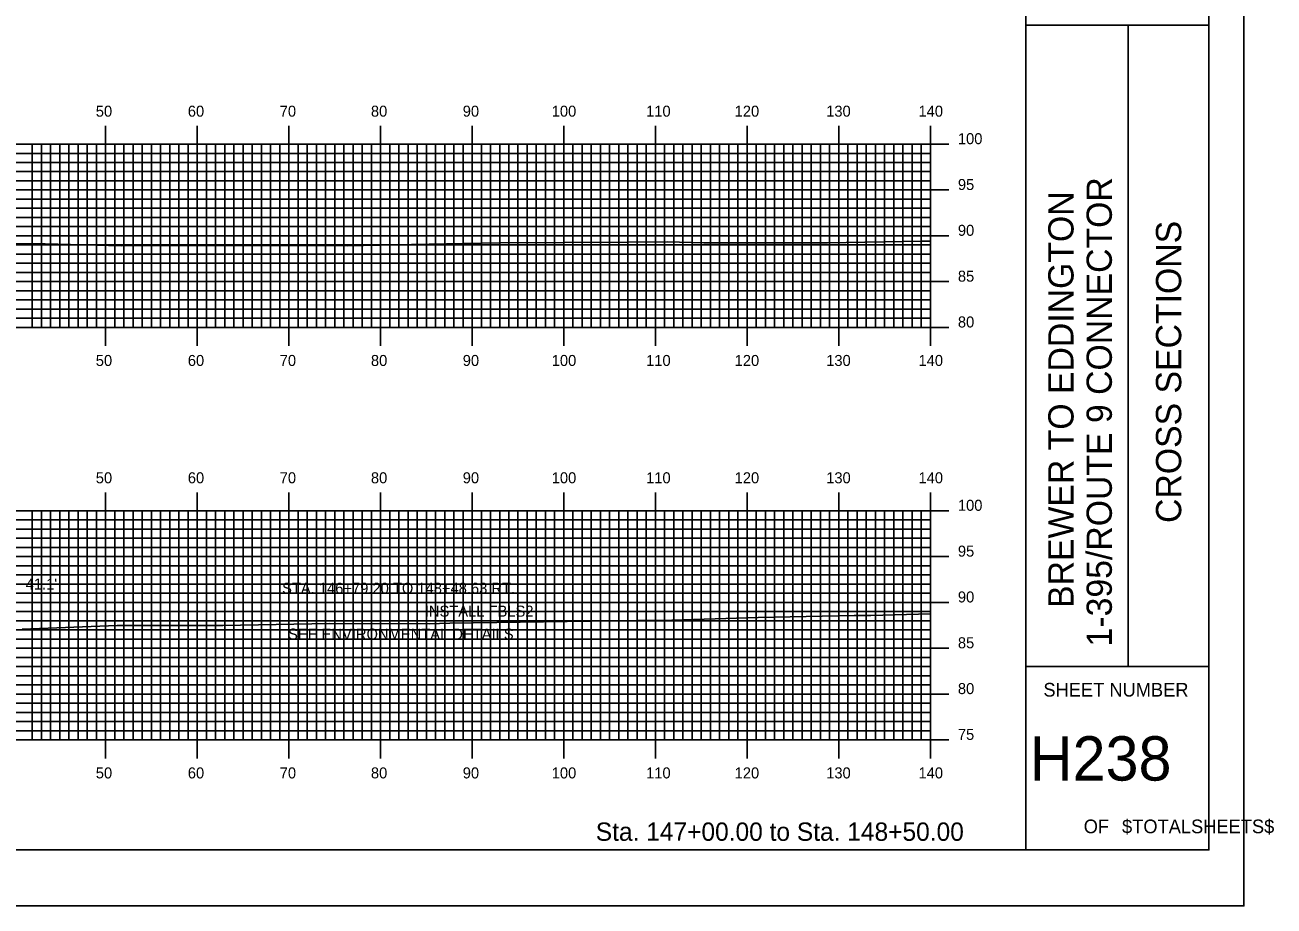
# Model space of a CAD drawing. Extents: x 1777925 to 1778268, y 442591 to 442811.
# Drawn here: x 1778132 to 1778268.3, y 442590.5 to 442686.7 of the extents above; entities that cross this region are included whole.
import ezdxf

# ---------------------------------------------------------------- set-up
doc = ezdxf.new("R2010")
doc.units = 0
for name, color, linetype in [('BORDER', 7, 'Continuous'), ('D_Text_Standard', 7, 'Continuous'), ('H_V ANNOTATION', 7, 'Continuous'), ('MAJOR', 7, 'Continuous'), ('MINOR', 7, 'Continuous'), ('PLOT BOUNDARY', 7, 'Continuous'), ('S_Roadway_Centerline', 7, 'Continuous')]:
    doc.layers.add(name, color=color, linetype=linetype)

msp = doc.modelspace()

# ---------------------------------------------------------------- linework, layer by layer
at = {"layer": 'BORDER'}
for p, q in [((1778241.19, 442596.67), (1778241.19, 442806.67)), ((1778241.19, 442686.67), (1778261.19, 442686.67)), ((1778252.37, 442616.67), (1778252.37, 442686.67)), ((1778241.19, 442616.67), (1778261.19, 442616.67))]:
    msp.add_line(p, q, dxfattribs=at)
msp.add_lwpolyline([(1777941.19, 442596.67), (1778261.19, 442596.67), (1778261.19, 442806.67), (1777941.19, 442806.67)], close=True, dxfattribs=at)
at = {"layer": 'MAJOR'}
for p, q in [((1778140.79, 442675.67), (1778140.79, 442673.67)), ((1778150.79, 442675.67), (1778150.79, 442673.67)), ((1778160.79, 442675.67), (1778160.79, 442673.67)), ((1778170.79, 442675.67), (1778170.79, 442673.67)), ((1778180.79, 442675.67), (1778180.79, 442673.67)), ((1778190.79, 442675.67), (1778190.79, 442673.67)), ((1778200.79, 442675.67), (1778200.79, 442673.67)), ((1778210.79, 442675.67), (1778210.79, 442673.67)), ((1778220.79, 442675.67), (1778220.79, 442673.67)), ((1778230.79, 442675.67), (1778230.79, 442673.67)), ((1777950.79, 442673.67), (1778230.79, 442673.67)), ((1777950.79, 442673.67), (1778230.79, 442673.67)), ((1778140.79, 442653.67), (1778140.79, 442673.67)), ((1778150.79, 442653.67), (1778150.79, 442673.67)), ((1778160.79, 442653.67), (1778160.79, 442673.67)), ((1778170.79, 442653.67), (1778170.79, 442673.67)), ((1778180.79, 442653.67), (1778180.79, 442673.67)), ((1778190.79, 442653.67), (1778190.79, 442673.67)), ((1778200.79, 442653.67), (1778200.79, 442673.67)), ((1778210.79, 442653.67), (1778210.79, 442673.67)), ((1778220.79, 442653.67), (1778220.79, 442673.67)), ((1778232.79, 442673.67), (1778228.79, 442673.67)), ((1778230.79, 442653.67), (1778230.79, 442673.67)), ((1778230.79, 442653.67), (1778230.79, 442673.67)), ((1777950.79, 442668.67), (1778230.79, 442668.67)), ((1778232.79, 442668.67), (1778228.79, 442668.67)), ((1777950.79, 442663.67), (1778230.79, 442663.67)), ((1778232.79, 442663.67), (1778228.79, 442663.67)), ((1777950.79, 442658.67), (1778230.79, 442658.67)), ((1778232.79, 442658.67), (1778228.79, 442658.67)), ((1777950.79, 442653.67), (1778230.79, 442653.67)), ((1777950.79, 442653.67), (1778230.79, 442653.67)), ((1778140.79, 442651.66), (1778140.79, 442653.67)), ((1778150.79, 442651.66), (1778150.79, 442653.67)), ((1778160.79, 442651.66), (1778160.79, 442653.67)), ((1778170.79, 442651.66), (1778170.79, 442653.67)), ((1778180.79, 442651.66), (1778180.79, 442653.67)), ((1778190.79, 442651.66), (1778190.79, 442653.67)), ((1778200.79, 442651.66), (1778200.79, 442653.67)), ((1778210.79, 442651.66), (1778210.79, 442653.67)), ((1778220.79, 442651.66), (1778220.79, 442653.67)), ((1778232.79, 442653.67), (1778228.79, 442653.67)), ((1778230.79, 442651.66), (1778230.79, 442653.67)), ((1778140.79, 442635.67), (1778140.79, 442633.67)), ((1778150.79, 442635.67), (1778150.79, 442633.67)), ((1778160.79, 442635.67), (1778160.79, 442633.67)), ((1778170.79, 442635.67), (1778170.79, 442633.67)), ((1778180.79, 442635.67), (1778180.79, 442633.67)), ((1778190.79, 442635.67), (1778190.79, 442633.67)), ((1778200.79, 442635.67), (1778200.79, 442633.67)), ((1778210.79, 442635.67), (1778210.79, 442633.67)), ((1778220.79, 442635.67), (1778220.79, 442633.67)), ((1778230.79, 442635.67), (1778230.79, 442633.67)), ((1777950.79, 442633.67), (1778230.79, 442633.67)), ((1777950.79, 442633.67), (1778230.79, 442633.67)), ((1778140.79, 442608.67), (1778140.79, 442633.67)), ((1778150.79, 442608.67), (1778150.79, 442633.67)), ((1778160.79, 442608.67), (1778160.79, 442633.67)), ((1778170.79, 442608.67), (1778170.79, 442633.67)), ((1778180.79, 442608.67), (1778180.79, 442633.67)), ((1778190.79, 442608.67), (1778190.79, 442633.67)), ((1778200.79, 442608.67), (1778200.79, 442633.67)), ((1778210.79, 442608.67), (1778210.79, 442633.67)), ((1778220.79, 442608.67), (1778220.79, 442633.67)), ((1778232.79, 442633.67), (1778228.79, 442633.67)), ((1778230.79, 442608.67), (1778230.79, 442633.67)), ((1778230.79, 442608.67), (1778230.79, 442633.67)), ((1777950.79, 442628.67), (1778230.79, 442628.67)), ((1778232.79, 442628.67), (1778228.79, 442628.67)), ((1777950.79, 442623.67), (1778230.79, 442623.67)), ((1778232.79, 442623.67), (1778228.79, 442623.67)), ((1777950.79, 442618.67), (1778230.79, 442618.67)), ((1778232.79, 442618.67), (1778228.79, 442618.67)), ((1777950.79, 442613.67), (1778230.79, 442613.67)), ((1778232.79, 442613.67), (1778228.79, 442613.67)), ((1777950.79, 442608.67), (1778230.79, 442608.67)), ((1777950.79, 442608.67), (1778230.79, 442608.67)), ((1778140.79, 442606.66), (1778140.79, 442608.67)), ((1778150.79, 442606.66), (1778150.79, 442608.67)), ((1778160.79, 442606.66), (1778160.79, 442608.67)), ((1778170.79, 442606.66), (1778170.79, 442608.67)), ((1778180.79, 442606.66), (1778180.79, 442608.67)), ((1778190.79, 442606.66), (1778190.79, 442608.67)), ((1778200.79, 442606.66), (1778200.79, 442608.67)), ((1778210.79, 442606.66), (1778210.79, 442608.67)), ((1778220.79, 442606.66), (1778220.79, 442608.67)), ((1778232.79, 442608.67), (1778228.79, 442608.67)), ((1778230.79, 442606.66), (1778230.79, 442608.67))]:
    msp.add_line(p, q, dxfattribs=at)
at = {"layer": 'MINOR'}
for p, q in [((1777950.79, 442672.67), (1778230.79, 442672.67)), ((1778132.79, 442653.67), (1778132.79, 442673.67)), ((1778133.79, 442653.67), (1778133.79, 442673.67)), ((1778134.79, 442653.67), (1778134.79, 442673.67)), ((1778135.79, 442653.67), (1778135.79, 442673.67)), ((1778136.79, 442653.67), (1778136.79, 442673.67)), ((1778137.79, 442653.67), (1778137.79, 442673.67)), ((1778138.79, 442653.67), (1778138.79, 442673.67)), ((1778139.79, 442653.67), (1778139.79, 442673.67)), ((1778141.79, 442653.67), (1778141.79, 442673.67)), ((1778142.79, 442653.67), (1778142.79, 442673.67)), ((1778143.79, 442653.67), (1778143.79, 442673.67)), ((1778144.79, 442653.67), (1778144.79, 442673.67)), ((1778145.79, 442653.67), (1778145.79, 442673.67)), ((1778146.79, 442653.67), (1778146.79, 442673.67)), ((1778147.79, 442653.67), (1778147.79, 442673.67)), ((1778148.79, 442653.67), (1778148.79, 442673.67)), ((1778149.79, 442653.67), (1778149.79, 442673.67)), ((1778151.79, 442653.67), (1778151.79, 442673.67)), ((1778152.79, 442653.67), (1778152.79, 442673.67)), ((1778153.79, 442653.67), (1778153.79, 442673.67)), ((1778154.79, 442653.67), (1778154.79, 442673.67)), ((1778155.79, 442653.67), (1778155.79, 442673.67)), ((1778156.79, 442653.67), (1778156.79, 442673.67)), ((1778157.79, 442653.67), (1778157.79, 442673.67)), ((1778158.79, 442653.67), (1778158.79, 442673.67)), ((1778159.79, 442653.67), (1778159.79, 442673.67)), ((1778161.79, 442653.67), (1778161.79, 442673.67)), ((1778162.79, 442653.67), (1778162.79, 442673.67)), ((1778163.79, 442653.67), (1778163.79, 442673.67)), ((1778164.79, 442653.67), (1778164.79, 442673.67)), ((1778165.79, 442653.67), (1778165.79, 442673.67)), ((1778166.79, 442653.67), (1778166.79, 442673.67)), ((1778167.79, 442653.67), (1778167.79, 442673.67)), ((1778168.79, 442653.67), (1778168.79, 442673.67)), ((1778169.79, 442653.67), (1778169.79, 442673.67)), ((1778171.79, 442653.67), (1778171.79, 442673.67)), ((1778172.79, 442653.67), (1778172.79, 442673.67)), ((1778173.79, 442653.67), (1778173.79, 442673.67)), ((1778174.79, 442653.67), (1778174.79, 442673.67)), ((1778175.79, 442653.67), (1778175.79, 442673.67)), ((1778176.79, 442653.67), (1778176.79, 442673.67)), ((1778177.79, 442653.67), (1778177.79, 442673.67)), ((1778178.79, 442653.67), (1778178.79, 442673.67)), ((1778179.79, 442653.67), (1778179.79, 442673.67)), ((1778181.79, 442653.67), (1778181.79, 442673.67)), ((1778182.79, 442653.67), (1778182.79, 442673.67)), ((1778183.79, 442653.67), (1778183.79, 442673.67)), ((1778184.79, 442653.67), (1778184.79, 442673.67)), ((1778185.79, 442653.67), (1778185.79, 442673.67)), ((1778186.79, 442653.67), (1778186.79, 442673.67)), ((1778187.79, 442653.67), (1778187.79, 442673.67)), ((1778188.79, 442653.67), (1778188.79, 442673.67)), ((1778189.79, 442653.67), (1778189.79, 442673.67)), ((1778191.79, 442653.67), (1778191.79, 442673.67)), ((1778192.79, 442653.67), (1778192.79, 442673.67)), ((1778193.79, 442653.67), (1778193.79, 442673.67)), ((1778194.79, 442653.67), (1778194.79, 442673.67)), ((1778195.79, 442653.67), (1778195.79, 442673.67)), ((1778196.79, 442653.67), (1778196.79, 442673.67)), ((1778197.79, 442653.67), (1778197.79, 442673.67)), ((1778198.79, 442653.67), (1778198.79, 442673.67)), ((1778199.79, 442653.67), (1778199.79, 442673.67)), ((1778201.79, 442653.67), (1778201.79, 442673.67)), ((1778202.79, 442653.67), (1778202.79, 442673.67)), ((1778203.79, 442653.67), (1778203.79, 442673.67)), ((1778204.79, 442653.67), (1778204.79, 442673.67)), ((1778205.79, 442653.67), (1778205.79, 442673.67)), ((1778206.79, 442653.67), (1778206.79, 442673.67)), ((1778207.79, 442653.67), (1778207.79, 442673.67)), ((1778208.79, 442653.67), (1778208.79, 442673.67)), ((1778209.79, 442653.67), (1778209.79, 442673.67)), ((1778211.79, 442653.67), (1778211.79, 442673.67)), ((1778212.79, 442653.67), (1778212.79, 442673.67)), ((1778213.79, 442653.67), (1778213.79, 442673.67)), ((1778214.79, 442653.67), (1778214.79, 442673.67)), ((1778215.79, 442653.67), (1778215.79, 442673.67)), ((1778216.79, 442653.67), (1778216.79, 442673.67)), ((1778217.79, 442653.67), (1778217.79, 442673.67)), ((1778218.79, 442653.67), (1778218.79, 442673.67)), ((1778219.79, 442653.67), (1778219.79, 442673.67)), ((1778221.79, 442653.67), (1778221.79, 442673.67)), ((1778222.79, 442653.67), (1778222.79, 442673.67)), ((1778223.79, 442653.67), (1778223.79, 442673.67)), ((1778224.79, 442653.67), (1778224.79, 442673.67)), ((1778225.79, 442653.67), (1778225.79, 442673.67)), ((1778226.79, 442653.67), (1778226.79, 442673.67)), ((1778227.79, 442653.67), (1778227.79, 442673.67)), ((1778228.79, 442653.67), (1778228.79, 442673.67)), ((1778230.79, 442672.67), (1778228.79, 442672.67)), ((1778229.79, 442653.67), (1778229.79, 442673.67)), ((1777950.79, 442671.67), (1778230.79, 442671.67)), ((1778230.79, 442671.67), (1778228.79, 442671.67)), ((1777950.79, 442670.67), (1778230.79, 442670.67)), ((1778230.79, 442670.67), (1778228.79, 442670.67)), ((1777950.79, 442669.67), (1778230.79, 442669.67)), ((1778230.79, 442669.67), (1778228.79, 442669.67)), ((1777950.79, 442667.67), (1778230.79, 442667.67)), ((1778230.79, 442667.67), (1778228.79, 442667.67)), ((1777950.79, 442666.67), (1778230.79, 442666.67)), ((1778230.79, 442666.67), (1778228.79, 442666.67)), ((1777950.79, 442665.67), (1778230.79, 442665.67)), ((1777950.79, 442664.67), (1778230.79, 442664.67)), ((1778230.79, 442665.67), (1778228.79, 442665.67)), ((1778230.79, 442664.67), (1778228.79, 442664.67)), ((1777950.79, 442662.67), (1778230.79, 442662.67)), ((1777950.79, 442661.67), (1778230.79, 442661.67)), ((1778230.79, 442662.67), (1778228.79, 442662.67)), ((1778230.79, 442661.67), (1778228.79, 442661.67)), ((1777950.79, 442660.67), (1778230.79, 442660.67)), ((1778230.79, 442660.67), (1778228.79, 442660.67)), ((1777950.79, 442659.67), (1778230.79, 442659.67)), ((1778230.79, 442659.67), (1778228.79, 442659.67)), ((1777950.79, 442657.67), (1778230.79, 442657.67)), ((1778230.79, 442657.67), (1778228.79, 442657.67)), ((1777950.79, 442656.67), (1778230.79, 442656.67)), ((1778230.79, 442656.67), (1778228.79, 442656.67)), ((1777950.79, 442655.67), (1778230.79, 442655.67)), ((1778230.79, 442655.67), (1778228.79, 442655.67)), ((1777950.79, 442654.67), (1778230.79, 442654.67)), ((1778230.79, 442654.67), (1778228.79, 442654.67)), ((1778132.79, 442608.67), (1778132.79, 442633.67)), ((1778133.79, 442608.67), (1778133.79, 442633.67)), ((1778134.79, 442608.67), (1778134.79, 442633.67)), ((1778135.79, 442608.67), (1778135.79, 442633.67)), ((1778136.79, 442608.67), (1778136.79, 442633.67)), ((1778137.79, 442608.67), (1778137.79, 442633.67)), ((1778138.79, 442608.67), (1778138.79, 442633.67)), ((1778139.79, 442608.67), (1778139.79, 442633.67)), ((1778141.79, 442608.67), (1778141.79, 442633.67)), ((1778142.79, 442608.67), (1778142.79, 442633.67)), ((1778143.79, 442608.67), (1778143.79, 442633.67)), ((1778144.79, 442608.67), (1778144.79, 442633.67)), ((1778145.79, 442608.67), (1778145.79, 442633.67)), ((1778146.79, 442608.67), (1778146.79, 442633.67)), ((1778147.79, 442608.67), (1778147.79, 442633.67)), ((1778148.79, 442608.67), (1778148.79, 442633.67)), ((1778149.79, 442608.67), (1778149.79, 442633.67)), ((1778151.79, 442608.67), (1778151.79, 442633.67)), ((1778152.79, 442608.67), (1778152.79, 442633.67)), ((1778153.79, 442608.67), (1778153.79, 442633.67)), ((1778154.79, 442608.67), (1778154.79, 442633.67)), ((1778155.79, 442608.67), (1778155.79, 442633.67)), ((1778156.79, 442608.67), (1778156.79, 442633.67)), ((1778157.79, 442608.67), (1778157.79, 442633.67)), ((1778158.79, 442608.67), (1778158.79, 442633.67)), ((1778159.79, 442608.67), (1778159.79, 442633.67)), ((1778161.79, 442608.67), (1778161.79, 442633.67)), ((1778162.79, 442608.67), (1778162.79, 442633.67)), ((1778163.79, 442608.67), (1778163.79, 442633.67)), ((1778164.79, 442608.67), (1778164.79, 442633.67)), ((1778165.79, 442608.67), (1778165.79, 442633.67)), ((1778166.79, 442608.67), (1778166.79, 442633.67)), ((1778167.79, 442608.67), (1778167.79, 442633.67)), ((1778168.79, 442608.67), (1778168.79, 442633.67)), ((1778169.79, 442608.67), (1778169.79, 442633.67)), ((1778171.79, 442608.67), (1778171.79, 442633.67)), ((1778172.79, 442608.67), (1778172.79, 442633.67)), ((1778173.79, 442608.67), (1778173.79, 442633.67)), ((1778174.79, 442608.67), (1778174.79, 442633.67)), ((1778175.79, 442608.67), (1778175.79, 442633.67)), ((1778176.79, 442608.67), (1778176.79, 442633.67)), ((1778177.79, 442608.67), (1778177.79, 442633.67)), ((1778178.79, 442608.67), (1778178.79, 442633.67)), ((1778179.79, 442608.67), (1778179.79, 442633.67)), ((1778181.79, 442608.67), (1778181.79, 442633.67)), ((1778182.79, 442608.67), (1778182.79, 442633.67)), ((1778183.79, 442608.67), (1778183.79, 442633.67)), ((1778184.79, 442608.67), (1778184.79, 442633.67)), ((1778185.79, 442608.67), (1778185.79, 442633.67)), ((1778186.79, 442608.67), (1778186.79, 442633.67)), ((1778187.79, 442608.67), (1778187.79, 442633.67)), ((1778188.79, 442608.67), (1778188.79, 442633.67)), ((1778189.79, 442608.67), (1778189.79, 442633.67)), ((1778191.79, 442608.67), (1778191.79, 442633.67)), ((1778192.79, 442608.67), (1778192.79, 442633.67)), ((1778193.79, 442608.67), (1778193.79, 442633.67)), ((1778194.79, 442608.67), (1778194.79, 442633.67)), ((1778195.79, 442608.67), (1778195.79, 442633.67)), ((1778196.79, 442608.67), (1778196.79, 442633.67)), ((1778197.79, 442608.67), (1778197.79, 442633.67)), ((1778198.79, 442608.67), (1778198.79, 442633.67)), ((1778199.79, 442608.67), (1778199.79, 442633.67)), ((1778201.79, 442608.67), (1778201.79, 442633.67)), ((1778202.79, 442608.67), (1778202.79, 442633.67)), ((1778203.79, 442608.67), (1778203.79, 442633.67)), ((1778204.79, 442608.67), (1778204.79, 442633.67)), ((1778205.79, 442608.67), (1778205.79, 442633.67)), ((1778206.79, 442608.67), (1778206.79, 442633.67)), ((1778207.79, 442608.67), (1778207.79, 442633.67)), ((1778208.79, 442608.67), (1778208.79, 442633.67)), ((1778209.79, 442608.67), (1778209.79, 442633.67)), ((1778211.79, 442608.67), (1778211.79, 442633.67)), ((1778212.79, 442608.67), (1778212.79, 442633.67)), ((1778213.79, 442608.67), (1778213.79, 442633.67)), ((1778214.79, 442608.67), (1778214.79, 442633.67)), ((1778215.79, 442608.67), (1778215.79, 442633.67)), ((1778216.79, 442608.67), (1778216.79, 442633.67)), ((1778217.79, 442608.67), (1778217.79, 442633.67)), ((1778218.79, 442608.67), (1778218.79, 442633.67)), ((1778219.79, 442608.67), (1778219.79, 442633.67)), ((1778221.79, 442608.67), (1778221.79, 442633.67)), ((1778222.79, 442608.67), (1778222.79, 442633.67)), ((1778223.79, 442608.67), (1778223.79, 442633.67)), ((1778224.79, 442608.67), (1778224.79, 442633.67)), ((1778225.79, 442608.67), (1778225.79, 442633.67)), ((1778226.79, 442608.67), (1778226.79, 442633.67)), ((1778227.79, 442608.67), (1778227.79, 442633.67)), ((1778228.79, 442608.67), (1778228.79, 442633.67)), ((1778229.79, 442608.67), (1778229.79, 442633.67)), ((1777950.79, 442632.67), (1778230.79, 442632.67)), ((1777950.79, 442631.67), (1778230.79, 442631.67)), ((1778230.79, 442632.67), (1778228.79, 442632.67)), ((1778230.79, 442631.67), (1778228.79, 442631.67)), ((1777950.79, 442630.67), (1778230.79, 442630.67)), ((1778230.79, 442630.67), (1778228.79, 442630.67)), ((1777950.79, 442629.67), (1778230.79, 442629.67)), ((1778230.79, 442629.67), (1778228.79, 442629.67)), ((1777950.79, 442627.67), (1778230.79, 442627.67)), ((1778230.79, 442627.67), (1778228.79, 442627.67)), ((1777950.79, 442626.67), (1778230.79, 442626.67)), ((1778230.79, 442626.67), (1778228.79, 442626.67)), ((1777950.79, 442625.67), (1778230.79, 442625.67)), ((1778230.79, 442625.67), (1778228.79, 442625.67)), ((1777950.79, 442624.67), (1778230.79, 442624.67)), ((1778230.79, 442624.67), (1778228.79, 442624.67)), ((1777950.79, 442622.67), (1778230.79, 442622.67)), ((1778230.79, 442622.67), (1778228.79, 442622.67)), ((1777950.79, 442621.67), (1778230.79, 442621.67)), ((1778230.79, 442621.67), (1778228.79, 442621.67)), ((1777950.79, 442620.67), (1778230.79, 442620.67)), ((1777950.79, 442619.67), (1778230.79, 442619.67)), ((1778230.79, 442620.67), (1778228.79, 442620.67)), ((1778230.79, 442619.67), (1778228.79, 442619.67)), ((1777950.79, 442617.67), (1778230.79, 442617.67)), ((1777950.79, 442616.67), (1778230.79, 442616.67)), ((1778230.79, 442617.67), (1778228.79, 442617.67)), ((1778230.79, 442616.67), (1778228.79, 442616.67)), ((1777950.79, 442615.67), (1778230.79, 442615.67)), ((1778230.79, 442615.67), (1778228.79, 442615.67)), ((1777950.79, 442614.67), (1778230.79, 442614.67)), ((1778230.79, 442614.67), (1778228.79, 442614.67)), ((1777950.79, 442612.67), (1778230.79, 442612.67)), ((1778230.79, 442612.67), (1778228.79, 442612.67)), ((1777950.79, 442611.67), (1778230.79, 442611.67)), ((1778230.79, 442611.67), (1778228.79, 442611.67)), ((1777950.79, 442610.67), (1778230.79, 442610.67)), ((1778230.79, 442610.67), (1778228.79, 442610.67)), ((1777950.79, 442609.67), (1778230.79, 442609.67)), ((1778230.79, 442609.67), (1778228.79, 442609.67))]:
    msp.add_line(p, q, dxfattribs=at)
at = {"layer": 'PLOT BOUNDARY'}
msp.add_lwpolyline([(1777925, 442590.55), (1778265, 442590.55), (1778265, 442810.55), (1777925, 442810.55)], close=True, dxfattribs=at)
at = {"layer": 'S_Roadway_Centerline'}
for points in [[(1778128.39, 442662.84), (1778134.18, 442662.79), (1778142.5, 442662.58), (1778151.74, 442662.62), (1778167.17, 442662.58), (1778174.18, 442662.71), (1778183.73, 442662.9), (1778197.83, 442662.98), (1778202.07, 442663.01), (1778206.06, 442662.89), (1778219.57, 442662.89), (1778229.78, 442663.07), (1778230.79, 442663.08)], [(1778131.69, 442620.77), (1778142.05, 442621.16), (1778153.59, 442621.17), (1778165.21, 442621.36), (1778176.15, 442621.35), (1778177.22, 442621.37), (1778178.36, 442621.41), (1778198.82, 442621.71), (1778201.4, 442621.71), (1778211.99, 442622.04), (1778222.47, 442622.23), (1778224.3, 442622.26), (1778230.79, 442622.43)]]:
    msp.add_lwpolyline(points, dxfattribs=at)

# ---------------------------------------------------------------- texts
at = {"layer": 'BORDER'}
for s, p in [('1-395/ROUTE 9 CONNECTOR', (1778250.59, 442618.87)), ('BREWER TO EDDINGTON', (1778246.41, 442623.07)), ('CROSS SECTIONS', (1778258.16, 442632.34))]:
    msp.add_text(s, height=2.7557, rotation=90, dxfattribs=at).set_placement(p)
for s, height, p in [('SHEET NUMBER', 1.4905, (1778243.12, 442613.4)), ('H238', 4.839, (1778241.63, 442604.23)), ('OF', 1.491, (1778247.52, 442598.49)), ('$TOTALSHEETS$', 1.4905, (1778251.7, 442598.49))]:
    msp.add_text(s, height=height, dxfattribs=at).set_placement(p)
at = {"layer": 'D_Text_Standard'}
for s, p in [("41.1'", (1778132.07, 442625.08)), ('STA. 146+79.20 TO 148+48.63 RT.', (1778160.05, 442624.62)), ('INSTALL FBLS2', (1778175.62, 442622.12)), ('SEE ENVIRONMENTAL DETAILS', (1778160.7, 442619.62))]:
    msp.add_text(s, height=1.2, dxfattribs=at).set_placement(p)
at = {"layer": 'H_V ANNOTATION'}
for s, height, p in [('50', 1.2, (1778139.72, 442676.67)), ('60', 1.2, (1778149.76, 442676.67)), ('70', 1.2, (1778159.79, 442676.67)), ('80', 1.2, (1778169.74, 442676.67)), ('90', 1.2, (1778179.76, 442676.67)), ('100', 1.2, (1778189.47, 442676.67)), ('110', 1.2, (1778199.77, 442676.67)), ('120', 1.2, (1778209.43, 442676.67)), ('130', 1.2, (1778219.42, 442676.67)), ('140', 1.2, (1778229.49, 442676.67)), ('100', 1.2, (1778233.79, 442673.67)), ('95', 1.2, (1778233.79, 442668.67)), ('90', 1.2, (1778233.79, 442663.67)), ('85', 1.2, (1778233.79, 442658.67)), ('80', 1.2, (1778233.79, 442653.67)), ('50', 1.2, (1778139.72, 442649.47)), ('60', 1.2, (1778149.76, 442649.47)), ('70', 1.2, (1778159.79, 442649.47)), ('80', 1.2, (1778169.74, 442649.47)), ('90', 1.2, (1778179.76, 442649.47)), ('100', 1.2, (1778189.47, 442649.47)), ('110', 1.2, (1778199.77, 442649.47)), ('120', 1.2, (1778209.43, 442649.47)), ('130', 1.2, (1778219.42, 442649.47)), ('140', 1.2, (1778229.49, 442649.47)), ('50', 1.2, (1778139.72, 442636.67)), ('60', 1.2, (1778149.76, 442636.67)), ('70', 1.2, (1778159.79, 442636.67)), ('80', 1.2, (1778169.74, 442636.67)), ('90', 1.2, (1778179.76, 442636.67)), ('100', 1.2, (1778189.47, 442636.67)), ('110', 1.2, (1778199.77, 442636.67)), ('120', 1.2, (1778209.43, 442636.67)), ('130', 1.2, (1778219.42, 442636.67)), ('140', 1.2, (1778229.49, 442636.67)), ('100', 1.2, (1778233.79, 442633.67)), ('95', 1.2, (1778233.79, 442628.67)), ('90', 1.2, (1778233.79, 442623.67)), ('85', 1.2, (1778233.79, 442618.67)), ('80', 1.2, (1778233.79, 442613.67)), ('75', 1.2, (1778233.79, 442608.67)), ('50', 1.2, (1778139.72, 442604.47)), ('60', 1.2, (1778149.76, 442604.47)), ('70', 1.2, (1778159.79, 442604.47)), ('80', 1.2, (1778169.74, 442604.47)), ('90', 1.2, (1778179.76, 442604.47)), ('100', 1.2, (1778189.47, 442604.47)), ('110', 1.2, (1778199.77, 442604.47)), ('120', 1.2, (1778209.43, 442604.47)), ('130', 1.2, (1778219.42, 442604.47)), ('140', 1.2, (1778229.49, 442604.47)), ('Sta. 147+00.00 to Sta. 148+50.00', 2.0004, (1778194.28, 442597.66))]:
    msp.add_text(s, height=height, dxfattribs=at).set_placement(p)

doc.saveas('drawing.dxf')
